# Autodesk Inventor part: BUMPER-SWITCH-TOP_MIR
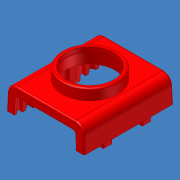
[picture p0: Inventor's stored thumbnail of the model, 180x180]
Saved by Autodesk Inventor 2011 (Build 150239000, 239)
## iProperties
Created: 2007-08
Part Number: BUMPER-SWITCH-TOP_MIR
Material: ABS Plastic
Document SubType Name: Modeling
Density: 1.06 g/cm^3
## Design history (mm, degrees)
derived "BUMPER-SWITCH-TOP.ipt"
body "Solid1"
tag "TaggingFeature2"
feature "DerivedBody::BUMPER-SWITCH-TOP.ipt" dims "d0" = 10
